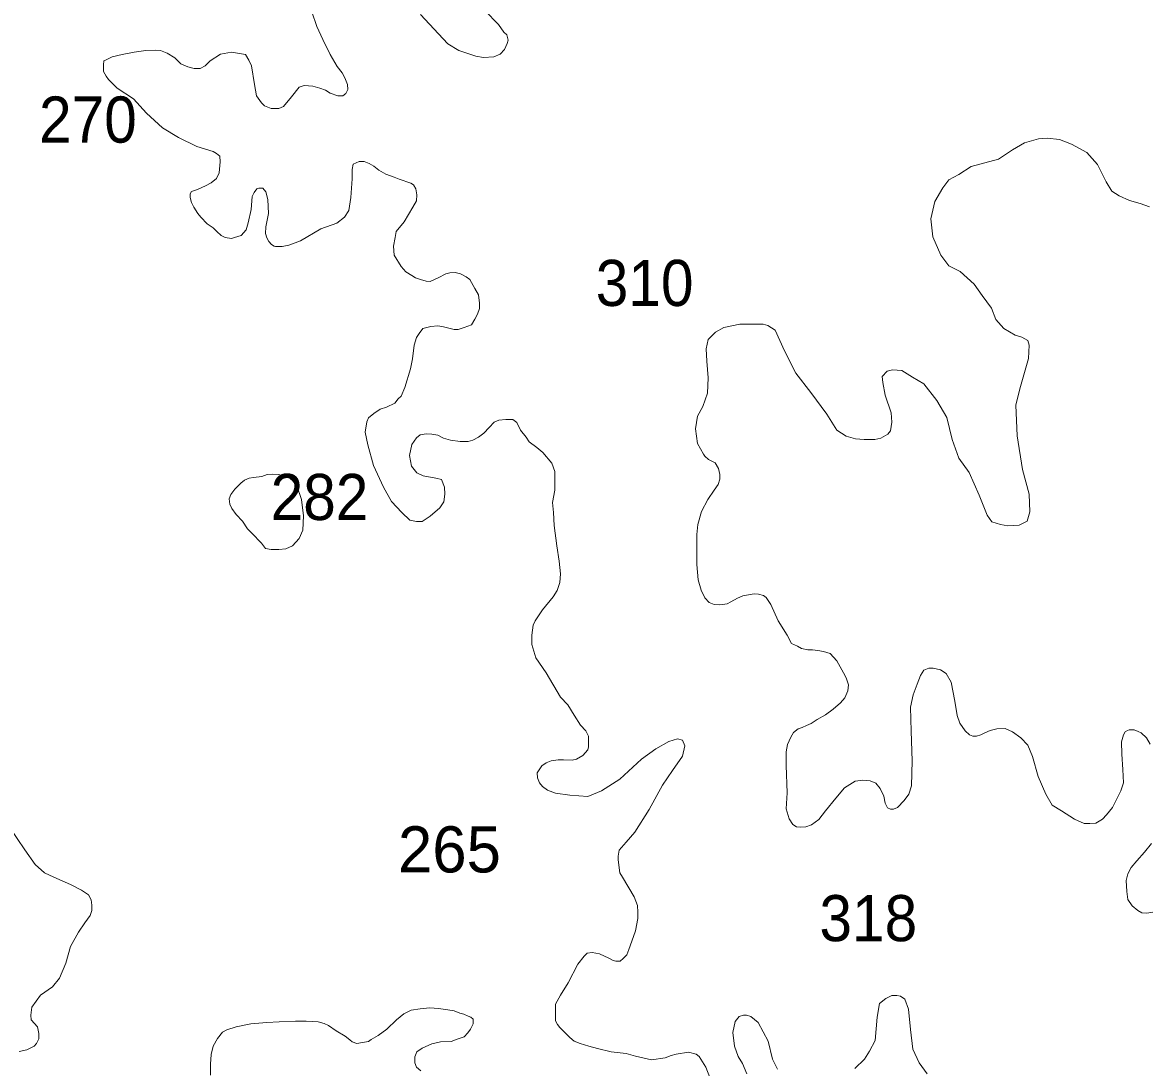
# Model space of a CAD drawing. Extents: x 445.4 to 500, y 8728.7 to 8784.
# Drawn here: x 490.167 to 494.076, y 8743.815 to 8747.44 of the extents above; entities that cross this region are included whole.
import ezdxf

# ---------------------------------------------------------------- set-up
doc = ezdxf.new("R2010")
doc.units = 0
doc.header["$LTSCALE"] = 0.064
doc.layers.add('2', color=7, linetype='Continuous', lineweight=13)
doc.layers.add('21', color=7, linetype='Continuous')

msp = doc.modelspace()

# ---------------------------------------------------------------- linework, layer by layer
at = {"layer": '2'}
for points in [[(491.1701, 8747.477), (491.1877, 8747.4261)], [(491.7702, 8747.4813), (491.8182, 8747.4326), (491.8361, 8747.4063), (491.8469, 8747.3967), (491.8516, 8747.3788), (491.8481, 8747.3669), (491.8385, 8747.3466), (491.8241, 8747.3298), (491.8014, 8747.3203), (491.7655, 8747.3179), (491.7392, 8747.3227), (491.6806, 8747.343), (491.6423, 8747.3657), (491.61, 8747.4003), (491.5478, 8747.4672)], [(491.1877, 8747.4261), (491.2091, 8747.3809), (491.2338, 8747.3282), (491.2584, 8747.2877), (491.276, 8747.2649), (491.2848, 8747.2473), (491.2936, 8747.2245), (491.2954, 8747.2069), (491.2883, 8747.1929), (491.2778, 8747.1858), (491.2602, 8747.1858), (491.2338, 8747.1946), (491.2179, 8747.2052), (491.1986, 8747.2122), (491.1739, 8747.2192), (491.144, 8747.221), (491.1264, 8747.2157), (491.1, 8747.1823), (491.0718, 8747.1489), (491.056, 8747.1419), (491.0296, 8747.1419), (491.0067, 8747.1507), (490.9961, 8747.1612), (490.9785, 8747.1858), (490.9715, 8747.2245), (490.9609, 8747.2895), (490.9521, 8747.3088), (490.9398, 8747.3282), (490.8923, 8747.3369), (490.8535, 8747.3299), (490.8183, 8747.3071), (490.8007, 8747.2895), (490.7831, 8747.2807), (490.762, 8747.2807), (490.7409, 8747.286), (490.7162, 8747.2965), (490.6951, 8747.3176), (490.6687, 8747.3334), (490.6458, 8747.3422), (490.6265, 8747.344), (490.5948, 8747.3422), (490.5543, 8747.3369), (490.5121, 8747.3282), (490.4777, 8747.3206), (490.4566, 8747.3101), (490.4495, 8747.3066), (490.4478, 8747.2925), (490.4478, 8747.2855), (490.4478, 8747.2697), (490.4566, 8747.2539), (490.4654, 8747.2416), (490.4953, 8747.2117), (490.5516, 8747.1748), (490.5974, 8747.1256), (490.652, 8747.0747), (490.7083, 8747.0413), (490.7717, 8747.0096), (490.828, 8746.9921), (490.8403, 8746.985), (490.8509, 8746.9763), (490.8526, 8746.9569), (490.8491, 8746.9183), (490.8403, 8746.8989), (490.821, 8746.8831), (490.8016, 8746.8726), (490.7736, 8746.861), (490.7525, 8746.854), (490.749, 8746.8452), (490.749, 8746.8329), (490.7525, 8746.8153), (490.7613, 8746.7995), (490.7754, 8746.7767), (490.7859, 8746.7644), (490.8071, 8746.7415), (490.8282, 8746.7275), (490.8405, 8746.7152), (490.8564, 8746.7011), (490.8704, 8746.6941), (490.8916, 8746.6906), (490.9021, 8746.6941), (490.925, 8746.7011), (490.9426, 8746.7204), (490.9496, 8746.745), (490.9602, 8746.7907), (490.9637, 8746.8364), (490.9708, 8746.8504), (490.9796, 8746.8627), (490.9866, 8746.8645), (491.0007, 8746.8645), (491.0113, 8746.8522), (491.0183, 8746.8258), (491.0201, 8746.7767), (491.0113, 8746.731), (491.0095, 8746.7081), (491.0148, 8746.6923), (491.0218, 8746.68), (491.0306, 8746.6695), (491.0394, 8746.6642), (491.0447, 8746.6624), (491.0676, 8746.6624), (491.0905, 8746.6677)], [(492.511, 8745.5067), (492.5054, 8745.5599), (492.5054, 8745.6636), (492.5096, 8745.6987), (492.5221, 8745.7431), (492.5446, 8745.7852), (492.5656, 8745.8174), (492.5797, 8745.837), (492.5853, 8745.8553), (492.5853, 8745.8721), (492.5811, 8745.8931), (492.5698, 8745.9127), (492.546, 8745.9239), (492.5333, 8745.9351), (492.5291, 8745.9422), (492.508, 8745.9795), (492.5011, 8746.0301), (492.508, 8746.0738), (492.5265, 8746.1082), (492.5426, 8746.1542), (492.5449, 8746.2071), (492.5403, 8746.2645), (492.538, 8746.3082), (492.5449, 8746.3404), (492.5702, 8746.3656), (492.6001, 8746.3817), (492.6554, 8746.3932), (492.6969, 8746.3932), (492.736, 8746.3932), (492.7521, 8746.3886), (492.7775, 8746.3725), (492.8097, 8746.3013), (492.8488, 8746.2232), (492.9018, 8746.1565), (492.9571, 8746.0807), (492.9916, 8746.0255), (493.0239, 8746.0048), (493.0561, 8745.9956), (493.086, 8745.9933), (493.1229, 8745.9933), (493.1436, 8745.9979), (493.1689, 8746.0117), (493.1781, 8746.0232), (493.1827, 8746.0531), (493.1804, 8746.0853), (493.1597, 8746.1473), (493.1505, 8746.191), (493.1482, 8746.2117), (493.1666, 8746.23), (493.185, 8746.2346), (493.2173, 8746.2323), (493.2541, 8746.2094), (493.2933, 8746.1864), (493.3382, 8746.1288), (493.3727, 8746.0691), (493.3912, 8745.9932), (493.4142, 8745.9289), (493.451, 8745.8783), (493.4856, 8745.8002), (493.5132, 8745.7312), (493.5296, 8745.7076), (493.5595, 8745.6984), (493.5849, 8745.6938), (493.624, 8745.6961), (493.6516, 8745.7099), (493.6608, 8745.742), (493.6585, 8745.8041), (493.6355, 8745.8891), (493.6171, 8746.0063), (493.6125, 8746.1121), (493.6263, 8746.1695), (493.6563, 8746.2744), (493.6586, 8746.3204), (493.654, 8746.3365), (493.6333, 8746.348), (493.6103, 8746.3549), (493.5711, 8746.3778), (493.5435, 8746.41), (493.5274, 8746.4491), (493.4952, 8746.4928), (493.4675, 8746.5318), (493.4192, 8746.5755), (493.38, 8746.5962), (493.3524, 8746.633), (493.3244, 8746.6965), (493.3175, 8746.7585), (493.3313, 8746.8183), (493.3589, 8746.8665), (493.3796, 8746.8941), (493.4142, 8746.9125), (493.4579, 8746.9401), (493.5524, 8746.9654), (493.6007, 8746.9975), (493.6422, 8747.0228), (493.6905, 8747.0366), (493.7205, 8747.0389), (493.7642, 8747.0343), (493.8057, 8747.0182), (493.8586, 8746.9883), (493.8955, 8746.947), (493.9254, 8746.8872)], [(491.0905, 8746.6677), (491.1309, 8746.6818), (491.2014, 8746.7239), (491.257, 8746.7433), (491.2834, 8746.7643), (491.2992, 8746.7872), (491.3063, 8746.8329), (491.3098, 8746.8979), (491.3098, 8746.9295), (491.3133, 8746.9488), (491.3345, 8746.9576), (491.3521, 8746.9576), (491.3697, 8746.9506), (491.3855, 8746.9418), (491.4031, 8746.9278), (491.4277, 8746.9137), (491.4559, 8746.9032), (491.4735, 8746.8961), (491.514, 8746.8821), (491.5228, 8746.8768), (491.5316, 8746.8627), (491.5351, 8746.8417), (491.5334, 8746.8206), (491.521, 8746.7995), (491.4911, 8746.7485), (491.463, 8746.7151), (491.4594, 8746.6941), (491.4542, 8746.6642), (491.4559, 8746.6326), (491.4806, 8746.5939), (491.4964, 8746.5746), (491.5175, 8746.5623), (491.5298, 8746.5535), (491.5474, 8746.5482), (491.5668, 8746.543), (491.5809, 8746.5412), (491.6091, 8746.5535), (491.6355, 8746.5676), (491.6495, 8746.5711), (491.6671, 8746.5728), (491.6865, 8746.5676), (491.7059, 8746.557), (491.7182, 8746.5482), (491.7363, 8746.5174), (491.7486, 8746.4946), (491.7521, 8746.4664), (491.7521, 8746.4471), (491.7451, 8746.4278), (491.7363, 8746.4102), (491.724, 8746.3909), (491.6993, 8746.3821), (491.6782, 8746.3751), (491.6641, 8746.3751), (491.6272, 8746.3839), (491.6078, 8746.3874), (491.5831, 8746.3856), (491.555, 8746.3786), (491.5427, 8746.361), (491.5339, 8746.347), (491.5251, 8746.3206), (491.5198, 8746.2732), (491.5127, 8746.238), (491.4932, 8746.1734), (491.4809, 8746.1435), (491.4703, 8746.1348), (491.458, 8746.1189), (491.4298, 8746.1049), (491.407, 8746.0979), (491.3858, 8746.0838), (491.3665, 8746.068), (491.3612, 8746.0539), (491.3559, 8746.0188), (491.3647, 8745.9749), (491.3841, 8745.9028), (491.4193, 8745.8273), (491.4473, 8745.7786), (491.4825, 8745.7399), (491.5107, 8745.7135), (491.5336, 8745.7083), (491.5529, 8745.7083), (491.5811, 8745.7276), (491.6145, 8745.7557), (491.6286, 8745.7768), (491.6321, 8745.8032), (491.6304, 8745.8278), (491.6198, 8745.8541), (491.6004, 8745.8594), (491.5564, 8745.8674), (491.5352, 8745.8779), (491.5159, 8745.9007), (491.5088, 8745.9376), (491.5176, 8745.9763), (491.5335, 8745.9991), (491.5458, 8746.0097), (491.5669, 8746.0132), (491.5863, 8746.0114), (491.6074, 8746.0079), (491.6268, 8745.9974), (491.6514, 8745.9903), (491.6849, 8745.9868), (491.713, 8745.9868)], [(493.9254, 8746.8872), (493.945, 8746.855), (493.9703, 8746.8389), (494.0072, 8746.8228), (494.044, 8746.8113), (494.0762, 8746.7998)], [(491.713, 8745.9868), (491.7289, 8745.9903), (491.7482, 8746.0009), (491.7676, 8746.0149), (491.7852, 8746.0343), (491.8028, 8746.0536), (491.8186, 8746.0606), (491.8433, 8746.0624), (491.8679, 8746.0624), (491.882, 8746.0518), (491.8943, 8746.0255), (491.9137, 8746.0009), (491.9243, 8745.9851), (491.9507, 8745.9658), (491.9718, 8745.9482), (492.0026, 8745.9116), (492.0133, 8745.8816), (492.0133, 8745.8173), (492.0048, 8745.7745), (492.009, 8745.7402), (492.0112, 8745.6952), (492.0198, 8745.6245), (492.0284, 8745.5709), (492.0327, 8745.5268), (492.0306, 8745.4968), (492.022, 8745.4689), (492.007, 8745.4475), (491.9705, 8745.4025), (491.9447, 8745.3639), (491.9383, 8745.3489), (491.934, 8745.3146), (491.934, 8745.2825), (491.9469, 8745.2353), (491.9834, 8745.1839), (492.0331, 8745.0988), (492.0589, 8745.0731), (492.0803, 8745.0367), (492.1018, 8745.0024), (492.1211, 8744.9831), (492.1297, 8744.9638), (492.1297, 8744.9445), (492.1297, 8744.9273), (492.1276, 8744.9166), (492.1104, 8744.8973), (492.0889, 8744.8845), (492.0739, 8744.8802), (492.0438, 8744.8823), (492.0245, 8744.8823), (492.0009, 8744.8781), (491.9837, 8744.8716), (491.9687, 8744.8609), (491.9515, 8744.8373), (491.9536, 8744.8195), (491.9601, 8744.8024), (491.9708, 8744.7895), (491.988, 8744.7766), (492.0159, 8744.7659), (492.0653, 8744.7595), (492.1275, 8744.7552), (492.1748, 8744.7745), (492.2392, 8744.8152), (492.3143, 8744.8838), (492.3637, 8744.9202), (492.4088, 8744.946), (492.4389, 8744.9545), (492.456, 8744.9502), (492.4646, 8744.9309), (492.456, 8744.8945), (492.4217, 8744.8452), (492.3873, 8744.7938), (492.3401, 8744.7102), (492.2907, 8744.6309), (492.2607, 8744.5966), (492.237, 8744.5687), (492.2327, 8744.5473), (492.2327, 8744.5345), (492.2392, 8744.4895), (492.2478, 8744.4744), (492.289, 8744.4066), (492.2997, 8744.3766), (492.3018, 8744.353), (492.3018, 8744.3315), (492.2933, 8744.2887), (492.2804, 8744.2523), (492.2696, 8744.2244), (492.2632, 8744.2051), (492.2503, 8744.1922), (492.2396, 8744.1837), (492.2245, 8744.1837), (492.216, 8744.1858), (492.2009, 8744.1944), (492.1687, 8744.2094), (492.143, 8744.2137), (492.1258, 8744.2115), (492.115, 8744.2008), (492.0936, 8744.173), (492.0592, 8744.1087), (492.0335, 8744.0658), (492.0159, 8744.0346), (492.0159, 8743.9981), (492.0159, 8743.9767)], [(493.716, 8744.763), (493.6893, 8744.8246), (493.6696, 8744.8933), (493.6537, 8744.9332), (493.6299, 8744.9584), (493.6004, 8744.9794), (493.5751, 8744.9906), (493.547, 8744.9892), (493.5232, 8744.9836), (493.5049, 8744.9752), (493.4909, 8744.9682), (493.4754, 8744.964), (493.4628, 8744.964), (493.4516, 8744.9682), (493.4361, 8744.9822), (493.4179, 8745.0088), (493.4094, 8745.0355), (493.401, 8745.0859), (493.3884, 8745.1518), (493.371, 8745.182), (493.3514, 8745.1947), (493.3261, 8745.2003), (493.3106, 8745.2003), (493.2938, 8745.1933), (493.2812, 8745.175), (493.2699, 8745.1442), (493.2559, 8745.1078), (493.2475, 8745.0643), (493.2488, 8744.9818), (493.253, 8744.8781), (493.2502, 8744.7912), (493.2417, 8744.7629), (493.2249, 8744.7404), (493.2024, 8744.7166), (493.1884, 8744.711), (493.1772, 8744.711), (493.1673, 8744.7152), (493.1589, 8744.732), (493.1547, 8744.7559), (493.1421, 8744.7825), (493.1266, 8744.8007), (493.107, 8744.8091), (493.0817, 8744.8119), (493.055, 8744.8077), (493.0185, 8744.7853), (492.9876, 8744.7488), (492.9525, 8744.7054), (492.9286, 8744.6746), (492.9034, 8744.6564), (492.8837, 8744.6493), (492.8654, 8744.6479), (492.8514, 8744.6493), (492.8388, 8744.6578), (492.8261, 8744.6774), (492.8163, 8744.7124), (492.8191, 8744.7671), (492.8163, 8744.8624), (492.8162, 8744.9095), (492.8204, 8744.9348), (492.8317, 8744.96), (492.8415, 8744.9768), (492.857, 8744.9894), (492.871, 8744.9936), (492.8864, 8745.0006), (492.9019, 8745.0076), (492.9229, 8745.0217), (492.9524, 8745.0385), (492.9791, 8745.0581), (493.0044, 8745.0791), (493.0198, 8745.0973), (493.0297, 8745.1212), (493.0325, 8745.1422), (493.024, 8745.166), (493.0142, 8745.1842), (492.9917, 8745.2249), (492.9678, 8745.2509), (492.9454, 8745.2579), (492.9257, 8745.2607), (492.9075, 8745.2635), (492.8906, 8745.2635), (492.8695, 8745.2677), (492.8555, 8745.2761), (492.8344, 8745.2859), (492.819, 8745.314), (492.7881, 8745.3644), (492.7628, 8745.4205), (492.7469, 8745.445), (492.7371, 8745.452), (492.7202, 8745.4562), (492.7048, 8745.4576), (492.6655, 8745.4506), (492.6472, 8745.4422), (492.6234, 8745.4296), (492.6107, 8745.4226), (492.5953, 8745.4212), (492.584, 8745.4198), (492.5658, 8745.4212), (492.5489, 8745.4282), (492.5335, 8745.4436), (492.5209, 8745.4702), (492.511, 8745.5067)], [(494.0782, 8744.9359), (494.0657, 8744.9585), (494.0476, 8744.9755), (494.0371, 8744.98), (494.0224, 8744.9856), (494.0168, 8744.9856), (494.0054, 8744.9856), (493.9998, 8744.9834), (493.9918, 8744.9788), (493.9862, 8744.9687), (493.9794, 8744.9449), (493.9805, 8744.902), (493.9839, 8744.8489), (493.9856, 8744.8022), (493.9771, 8744.7742), (493.9617, 8744.7448), (493.9477, 8744.7167), (493.9266, 8744.6915), (493.9126, 8744.6761), (493.8901, 8744.6621), (493.869, 8744.6607), (493.8494, 8744.6607), (493.8157, 8744.6761), (493.7707, 8744.7055), (493.7384, 8744.7251), (493.716, 8744.763)], [(490.1554, 8743.8704), (490.1814, 8743.8763), (490.2073, 8743.8883), (490.2153, 8743.8983), (490.2233, 8743.9142), (490.2233, 8743.9321), (490.2193, 8743.956), (490.1974, 8743.9799), (490.1954, 8743.9959), (490.1994, 8744.0238), (490.2293, 8744.0656), (490.2715, 8744.0949), (490.2955, 8744.1247), (490.3175, 8744.1765), (490.3334, 8744.2343), (490.3614, 8744.2841), (490.3833, 8744.316), (490.4013, 8744.3419), (490.4073, 8744.3598), (490.4073, 8744.3778), (490.4053, 8744.3957), (490.3953, 8744.4136), (490.3713, 8744.4296), (490.3334, 8744.4495), (490.2755, 8744.4754), (490.2431, 8744.4905), (490.2112, 8744.5184), (490.1752, 8744.5702), (490.1214, 8744.6479)], [(494.0874, 8744.3535), (494.067, 8744.3501), (494.0489, 8744.3513), (494.0353, 8744.3592), (494.016, 8744.375), (494.0013, 8744.3976), (493.9979, 8744.4247), (493.9956, 8744.4631), (494.0013, 8744.4869), (494.0126, 8744.5084), (494.0319, 8744.531), (494.0591, 8744.5615), (494.0828, 8744.592)], [(493.0537, 8743.8116), (493.088, 8743.8437), (493.1052, 8743.8716), (493.1245, 8743.908), (493.131, 8743.9895), (493.1396, 8744.0366), (493.161, 8744.0538), (493.1825, 8744.0645), (493.1997, 8744.0645), (493.2126, 8744.0623), (493.2276, 8744.0516), (493.2405, 8744.0173), (493.2469, 8743.9466), (493.2555, 8743.878), (493.277, 8743.8309), (493.3049, 8743.7923)], [(491.6978, 8743.9996), (491.6843, 8744.003), (491.664, 8744.0114), (491.6421, 8744.0148), (491.61, 8744.0198), (491.5796, 8744.0215), (491.5458, 8744.0182), (491.5154, 8744.0131), (491.49, 8744.0013), (491.4647, 8743.9794), (491.4309, 8743.9473), (491.4005, 8743.9254), (491.3768, 8743.9119), (491.3667, 8743.9052), (491.3464, 8743.9018), (491.3261, 8743.8984), (491.3109, 8743.9035), (491.3025, 8743.9102), (491.2856, 8743.9237), (491.2552, 8743.9423), (491.2282, 8743.9608), (491.2129, 8743.9676), (491.1919, 8743.9725), (491.1513, 8743.9758), (491.1141, 8743.9758), (491.0567, 8743.9725), (491.0145, 8743.9708), (490.9587, 8743.9657), (490.908, 8743.9556), (490.8759, 8743.9455), (490.8607, 8743.9371), (490.8438, 8743.9151), (490.8286, 8743.8881), (490.8218, 8743.8595), (490.8185, 8743.8257), (490.8185, 8743.7886)], [(491.5487, 8743.8032), (491.5335, 8743.8153), (491.5274, 8743.8305), (491.5274, 8743.8517), (491.535, 8743.8684), (491.5532, 8743.8821), (491.5867, 8743.8972), (491.6171, 8743.9033), (491.6536, 8743.9048), (491.6748, 8743.9124), (491.6992, 8743.9215), (491.7113, 8743.9352), (491.7204, 8743.9473), (491.7299, 8743.9659), (491.7299, 8743.9827), (491.7215, 8743.9895), (491.713, 8743.9929), (491.6978, 8743.9996)], [(492.6793, 8743.7924), (492.6643, 8743.8288), (492.6492, 8743.8524), (492.6364, 8743.8888), (492.6307, 8743.9359), (492.6393, 8743.9745), (492.6522, 8743.9916), (492.6672, 8743.9959), (492.678, 8743.9959), (492.693, 8743.9916), (492.7187, 8743.9702), (492.7531, 8743.9059), (492.7681, 8743.8437), (492.7853, 8743.8094)], [(492.0159, 8743.9767), (492.0223, 8743.9638), (492.0309, 8743.9531), (492.0459, 8743.9381), (492.0652, 8743.9188), (492.0803, 8743.906), (492.1017, 8743.8974), (492.1318, 8743.8888), (492.1619, 8743.8803), (492.2091, 8743.8695), (492.2606, 8743.8631), (492.2928, 8743.8545), (492.3486, 8743.8417), (492.3959, 8743.8481), (492.4174, 8743.8567), (492.4345, 8743.861), (492.4775, 8743.8674), (492.5032, 8743.861), (492.514, 8743.8524), (492.5376, 8743.816), (492.5505, 8743.7795)]]:
    msp.add_lwpolyline(points, dxfattribs=at)
msp.add_lwpolyline([(490.962, 8745.6687), (490.9959, 8745.6335), (491.0103, 8745.6153), (491.0298, 8745.6114), (491.0559, 8745.6114), (491.0807, 8745.614), (491.1029, 8745.6244), (491.1264, 8745.6492), (491.1394, 8745.6791), (491.142, 8745.7286), (491.1342, 8745.7846), (491.1185, 8745.8327), (491.1029, 8745.851), (491.0885, 8745.864), (491.0755, 8745.8666), (491.0533, 8745.8718), (491.0351, 8745.8731), (491.0155, 8745.8718), (490.9972, 8745.8653), (490.9685, 8745.8614), (490.9529, 8745.8588), (490.9372, 8745.8523), (490.9242, 8745.8418), (490.9033, 8745.821), (490.889, 8745.8028), (490.8837, 8745.7872), (490.8863, 8745.7689), (490.8929, 8745.7533), (490.9085, 8745.7325), (490.9294, 8745.7104), (490.9477, 8745.683)], close=True, dxfattribs=at)

# ---------------------------------------------------------------- texts
at = {"layer": '21', "width": 0.95}
for s, p in [('270', (490.2242, 8747.0231)), ('310', (492.1553, 8746.4564)), ('282', (491.0275, 8745.7138)), ('318', (492.9311, 8744.2528))]:
    msp.add_text(s, height=0.16, dxfattribs=at).set_placement(p)
at = {"layer": '21'}
msp.add_text('265', height=0.16, dxfattribs=at).set_placement((491.4693, 8744.4913))

doc.saveas('drawing.dxf')
